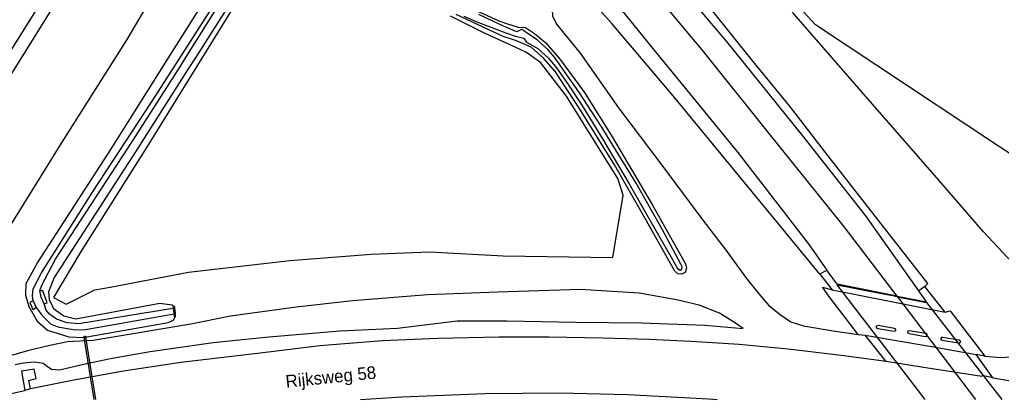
# Model space of a CAD drawing. Extents: x 135999 to 138000, y 396000 to 398501.
# Drawn here: x 136900.1 to 137094.8, y 396000 to 396075.3 of the extents above; entities that cross this region are included whole.
import ezdxf

# ---------------------------------------------------------------- set-up
doc = ezdxf.new("R2010")
doc.units = 0
for name, color, linetype in [('gg-anno-openbare ruimte label', 7, 'Continuous'), ('gg-knt-BGT kruinlijn', 7, 'Continuous'), ('gg-kwrk-faunavoorziening', 7, 'Continuous'), ('gg-kwrk-kunstwerk niveau 01', 7, 'Continuous'), ('gx-grn-maaiveld', 7, 'Continuous')]:
    doc.layers.add(name, color=color, linetype=linetype)

msp = doc.modelspace()

# ---------------------------------------------------------------- linework, layer by layer
at = {"layer": 'gg-knt-BGT kruinlijn'}
for p, q in [((136904.21, 396073.75), (136916.78, 396093.97)), ((137017.53, 396074.52), (137014.24, 396078.15)), ((137045.54, 396067.01), (137036.97, 396077.71)), ((136887.98, 396047.74), (136904.21, 396073.75)), ((137029.71, 396060.21), (137017.53, 396074.52)), ((137052.73, 396058.2), (137045.54, 396067.01)), ((137051.53, 396033.65), (137029.71, 396060.21)), ((137060.34, 396048.37), (137052.73, 396058.2)), ((137069.27, 396036.93), (137060.34, 396048.37)), ((137080.21, 396022.99), (137069.27, 396036.93)), ((137058.74, 396024.8), (137051.53, 396033.65)), ((137058.74, 396024.8), (137061.22, 396021.71)), ((137079.6, 396022.4), (137080.21, 396022.99)), ((137061.22, 396021.71), (137083.64, 396017.27)), ((137083.64, 396017.27), (137079.6, 396022.4)), ((136975.05, 396014.13), (136986.88, 396015.56)), ((136986.88, 396015.56), (136996.73, 396015.54)), ((136996.73, 396015.54), (137010.39, 396015.34)), ((137010.39, 396015.34), (137023.4, 396015.2)), ((137023.4, 396015.2), (137035.95, 396014.71)), ((136949.49, 396012.43), (136963.62, 396013.59)), ((136963.62, 396013.59), (136975.05, 396014.13)), ((137035.95, 396014.71), (137043.58, 396014.08)), ((136925.97, 396009.5), (136938.46, 396011.25)), ((136938.46, 396011.25), (136949.49, 396012.43)), ((136918.46, 396008.15), (136925.97, 396009.5)), ((136899.21, 396006.89), (136900.87, 396007.26)), ((136900.87, 396007.26), (136903.02, 396007.44)), ((136903.02, 396007.44), (136904.76, 396007.19)), ((136904.76, 396007.19), (136905.58, 396006.59)), ((136913.07, 396007.05), (136918.46, 396008.15)), ((136905.58, 396006.59), (136906.38, 396006.01)), ((136906.38, 396006.01), (136907.99, 396005.83)), ((136907.99, 396005.83), (136913.07, 396007.05))]:
    msp.add_line(p, q, dxfattribs=at)
at = {"layer": 'gg-kwrk-faunavoorziening'}
msp.add_lwpolyline([(136914.86, 396000), (136912.97, 396011.88), (136912.87, 396012.5), (136913.12, 396012.54), (136913.22, 396011.92), (136915.11, 396000)], dxfattribs=at)
at = {"layer": 'gg-kwrk-kunstwerk niveau 01'}
msp.add_line((137074.2, 396020.36), (137089.62, 396000), dxfattribs=at)
for points in [[(137079.66, 396000), (137062.2, 396022.74), (137068.62, 396021.47), (137073.51, 396020.5), (137074.2, 396020.36)], [(137074.2, 396020.36), (137079.89, 396019.23), (137094.88, 396000)]]:
    msp.add_lwpolyline(points, dxfattribs=at)
at = {"layer": 'gx-grn-maaiveld'}
for p, q in [((137060.17, 396025.64), (137058.74, 396024.8)), ((137079.6, 396022.4), (137078.39, 396021.55)), ((136902.79, 396019.56), (136903.39, 396018.22)), ((136930.7, 396016.97), (136930.62, 396018.08)), ((137066.39, 396012.88), (137067.78, 396012.7)), ((137071.89, 396007.51), (137067.78, 396012.7)), ((137093.09, 396004.3), (137089.79, 396008.9)), ((137091.48, 396008.59), (137089.79, 396008.9)), ((136893, 396000), (136901.15, 396001.73)), ((136902.26, 396002.09), (136901.15, 396001.73))]:
    msp.add_line(p, q, dxfattribs=at)
for points in [[(136862.22, 396002.29), (136869.35, 396004.41), (136875.44, 396006.74), (136878.71, 396008.38), (136882.32, 396011.02), (136885.93, 396014.61), (136889.92, 396020.33), (136898.11, 396034.15), (136908.51, 396051.01), (136921.41, 396071.33), (136934.2, 396093.01), (136946.4, 396113.73), (136950.49, 396120.78), (136951.21, 396122.82), (136951.4, 396125.21), (136951.09, 396127.34), (136950.41, 396129.56), (136948.6, 396134.53), (136946.17, 396138.16)], [(136935.2, 396126.34), (136933.81, 396125.7), (136914.1, 396094.43), (136887.02, 396051.29), (136868.6, 396022.27)], [(136958.14, 396112.61), (136957.75, 396112.22), (136938.5, 396081.98), (136930.31, 396068.97), (136918.09, 396049.54), (136903.69, 396027.29), (136901.35, 396022.9), (136901.25, 396020.67), (136901.89, 396018.41), (136903.59, 396015.51), (136905.62, 396013.74), (136909.86, 396012.37), (136912.7, 396012.29), (136929.51, 396015.27), (136930.61, 396015.72), (136930.94, 396016.37)], [(136962.58, 396109.6), (136958.78, 396104.56), (136952.32, 396095.11), (136942.3, 396079.36), (136935.14, 396068.08), (136933.52, 396065.52), (136923.09, 396049.08), (136906.91, 396024.18), (136905.79, 396021.29), (136905.92, 396019.79), (136906.8, 396018.02), (136908.84, 396016.55), (136911.23, 396015.99), (136927.89, 396019.05), (136930.32, 396018.73), (136930.8, 396018.36)], [(137105.99, 396042.39), (137057.93, 396074.24), (137035.22, 396099), (137038.35, 396101.46)], [(137098.68, 396008.54), (137101.36, 396009.36), (137104.81, 396010.33), (137106.34, 396012.19), (137106.37, 396014.58), (137105.38, 396017.53), (137100.81, 396022.96), (137091.21, 396033.2), (137082.39, 396043.48), (137069.19, 396058.51), (137053.62, 396076.42), (137042.05, 396089.58), (137039.38, 396091.99), (137036.71, 396094.11), (137033.56, 396095.48), (137031.74, 396095.69), (137030.27, 396095.76), (137027.13, 396093.6), (137025.15, 396091.8)], [(137078.39, 396021.55), (137067.89, 396036.39), (137055.41, 396052.25), (137040.27, 396071.03), (137029.05, 396084.34)], [(137011.15, 396081.77), (137006.41, 396078.53), (137005.68, 396077.2), (137005.74, 396076.08), (137006.56, 396074.43), (137011.23, 396068.64), (137018.85, 396057.82), (137027.45, 396046.44), (137035.54, 396035.5), (137040.21, 396029.49), (137044.21, 396023.96), (137046.64, 396020.9), (137048.66, 396018.61), (137050.88, 396016.8), (137053.05, 396015.37), (137055.55, 396014.57), (137061.38, 396013.6), (137066.39, 396012.88)], [(137074.11, 396020.48), (137063.68, 396034.14), (137048.43, 396053.04), (137035.42, 396069.31), (137025.18, 396081.57)], [(136902.79, 396019.56), (136902.61, 396020.56), (136902.8, 396021.91), (136904.44, 396025.09), (136914.53, 396041.1), (136926.25, 396058.93), (136931.71, 396067.47), (136939.4, 396079.51)], [(136904.12, 396021.49), (136904.52, 396022.67), (136907.22, 396027.79), (136922.45, 396051.22), (136931.99, 396066.1), (136932.39, 396066.74), (136940.05, 396078.97)], [(136989.74, 396077.52), (136995.13, 396075.09), (136996.8, 396074.49), (136998.93, 396073.83), (137000.41, 396073.75), (137002.19, 396072.52), (137004.41, 396070.71), (137007.25, 396067.39), (137012.11, 396060.82), (137017.6, 396052.06), (137025.57, 396038.49), (137032.13, 396026.86), (137032.32, 396026.02), (137032.04, 396025.15), (137031.43, 396024.8), (137030.64, 396024.91), (137030.02, 396025.42), (137024.16, 396035.87), (137018.06, 396046.48), (137011.44, 396057.13)], [(137019.3, 396077.37), (137025.86, 396069.34), (137042.5, 396048.93), (137056.68, 396030.67), (137060.17, 396025.64)], [(136925.36, 396050.17), (136912.13, 396029.19), (136906.8, 396020.17), (136909.34, 396018.85), (136914.98, 396021.73), (136918.02, 396022.27), (136933.6, 396025.19), (136953.67, 396027.56), (136969.8, 396028.76), (136981.34, 396029.25), (136996, 396028.49), (137017.69, 396028.16), (137019.75, 396040.49), (137018.74, 396043.77), (137008.51, 396060.13), (137003.43, 396066.7), (137000.63, 396068.79), (136998.37, 396069.86), (136992.11, 396072.65), (136985.54, 396075.96)], [(136941.93, 396076.84), (136925.36, 396050.17)], [(137011.44, 396057.13), (137006.34, 396064.97), (137003.95, 396067.66), (137001.51, 396069.84), (136998.96, 396070.94), (136998, 396071.26), (136995.98, 396071.96), (136990.88, 396074.31), (136986.67, 396076.32)], [(136988.18, 396076.01), (136991.05, 396074.74), (136996.48, 396072.71), (136998.44, 396072.04), (137000.09, 396071.65), (137000.58, 396070.86), (137002.85, 396069.54), (137004.93, 396067.64), (137006.52, 396065.75), (137008.7, 396062.65), (137011.69, 396058.17), (137015.67, 396051.68), (137020.95, 396042.73), (137024.7, 396036.1), (137029.8, 396027.3), (137030.55, 396025.98), (137031.06, 396025.62), (137031.39, 396025.82), (137031.44, 396026.28), (137031.23, 396026.82), (137027.57, 396033.64), (137022.35, 396042.86)], [(137022.35, 396042.86), (137015.43, 396054.18), (137010.99, 396061.01), (137008.29, 396064.84), (137006.15, 396067.88), (137004.9, 396069.32), (137002.77, 396071.23), (137000.1, 396073.08), (136999.72, 396073.42), (136998.71, 396072.9), (136996.63, 396073.74), (136994.05, 396074.91), (136991.12, 396076.29)], [(137074.11, 396020.48), (137062.22, 396022.84), (137060.17, 396025.64)], [(137030.37, 396019.74), (137022.96, 396021.04), (137011.29, 396021.78), (136994.89, 396021.27), (136980.97, 396020.76), (136966.14, 396019.56), (136954.92, 396018.25), (136941.92, 396016.48), (136934.04, 396014.89), (136914.7, 396011.67), (136909.57, 396011.41), (136906.05, 396010.69), (136901.65, 396009.62), (136897.56, 396008.45), (136896.02, 396007.3), (136894.87, 396005.89), (136883.12, 396001.6)], [(136904.93, 396018.93), (136904.35, 396020.29), (136904.12, 396021.49)], [(136904.93, 396018.93), (136905.56, 396019.15), (136904.71, 396021.49), (136904.12, 396021.49)], [(137066.39, 396012.88), (137060.58, 396020.46), (137059.3, 396022.23), (137061.22, 396021.71)], [(137074.11, 396020.48), (137079.91, 396019.33), (137078.39, 396021.55)], [(136902.79, 396019.56), (136902.11, 396019.22), (136902.72, 396017.79), (136903.39, 396018.22)], [(136930.62, 396018.08), (136930.06, 396017.98), (136911.86, 396015.01), (136909.51, 396015.17), (136907.42, 396015.92), (136905.92, 396016.95), (136905.35, 396017.71), (136904.93, 396018.93)], [(137043.58, 396014.08), (137042.03, 396015.12), (137038.86, 396017.08), (137034.82, 396018.7), (137030.37, 396019.74)], [(136903.39, 396018.22), (136904.58, 396016.64), (136906.18, 396014.96), (136907.65, 396014.4), (136911.1, 396013.78), (136913.17, 396013.88), (136930.7, 396016.97)], [(136930.62, 396018.08), (136930.61, 396018.35), (136930.8, 396018.36)], [(136930.7, 396016.97), (136930.74, 396016.36), (136930.94, 396016.37)], [(136930.8, 396018.36), (136930.82, 396018.09), (136930.9, 396016.99), (136930.94, 396016.37)], [(137083.64, 396017.27), (137084.63, 396017.57), (137086.24, 396015.37), (137091.48, 396008.59)], [(137070.07, 396014.58), (137069.94, 396014.44), (137069.95, 396014.24), (137070.24, 396014.08), (137073.46, 396013.53), (137073.74, 396013.57), (137073.87, 396013.71), (137073.86, 396013.91), (137073.58, 396014.08), (137070.35, 396014.62), (137070.07, 396014.58)], [(137076.28, 396013.54), (137076.15, 396013.4), (137076.16, 396013.19), (137076.45, 396013.03), (137079.67, 396012.48), (137079.95, 396012.52), (137080.08, 396012.66), (137080.07, 396012.87), (137079.79, 396013.03), (137076.56, 396013.58), (137076.28, 396013.54)], [(137071.89, 396007.51), (137067.51, 396008.12), (137063.02, 396008.69), (137052.48, 396009.97), (137042.78, 396010.85), (137033.27, 396011.46), (137024.96, 396011.86), (137015.77, 396012.16), (137005, 396012.33), (136995.15, 396012.33), (136983.08, 396012.08), (136972.03, 396011.6), (136959.64, 396010.6), (136947.25, 396009.08), (136932.07, 396007.31), (136920.71, 396005.56), (136910.83, 396003.79), (136902.26, 396002.09)], [(137067.78, 396012.7), (137080.9, 396010.47), (137089.79, 396008.9)], [(137082.88, 396012.24), (137082.75, 396012.09), (137082.77, 396011.89), (137083.05, 396011.73), (137086.27, 396011.18), (137086.55, 396011.22), (137086.68, 396011.36), (137086.67, 396011.56), (137086.39, 396011.73), (137083.16, 396012.27), (137082.88, 396012.24)], [(137093.09, 396004.3), (137090.96, 396004.71), (137090.92, 396004.53), (137078.92, 396006.4), (137071.89, 396007.51)], [(137091.48, 396008.59), (137094.73, 396008.29), (137098.68, 396008.54)], [(136902.26, 396002.09), (136901.94, 396003.71), (136903.36, 396004.11), (136902.98, 396006), (136900.44, 396005.58), (136901.15, 396001.73)], [(137093.09, 396004.3), (137098.21, 396003.38), (137102.14, 396002.65), (137113.43, 396000.37), (137115.02, 396000)], [(136967.7, 396000), (136975.85, 396000.52), (136992.42, 396001.13), (137007.24, 396001.27), (137020.72, 396000.97), (137036.7, 396000.13), (137038.38, 396000)]]:
    msp.add_lwpolyline(points, dxfattribs=at)

# ---------------------------------------------------------------- texts
at = {"layer": 'gg-anno-openbare ruimte label'}
msp.add_text('Rijksweg 58', height=2.5, rotation=5.9, dxfattribs=at).set_placement((136952.96, 396002.29))

doc.saveas('drawing.dxf')
